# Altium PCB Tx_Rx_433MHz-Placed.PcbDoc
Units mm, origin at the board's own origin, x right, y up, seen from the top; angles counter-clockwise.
Board outline 100 x 100 mm, 4 copper layers (SIGNAL_1, SIGNAL_2, SIGNAL_3, SIGNAL_4), stack 1.58 mm thick; 85 components, 84 nets, 318 pads, 0 vias.
Unrouted connection lines stored in the file: 208.
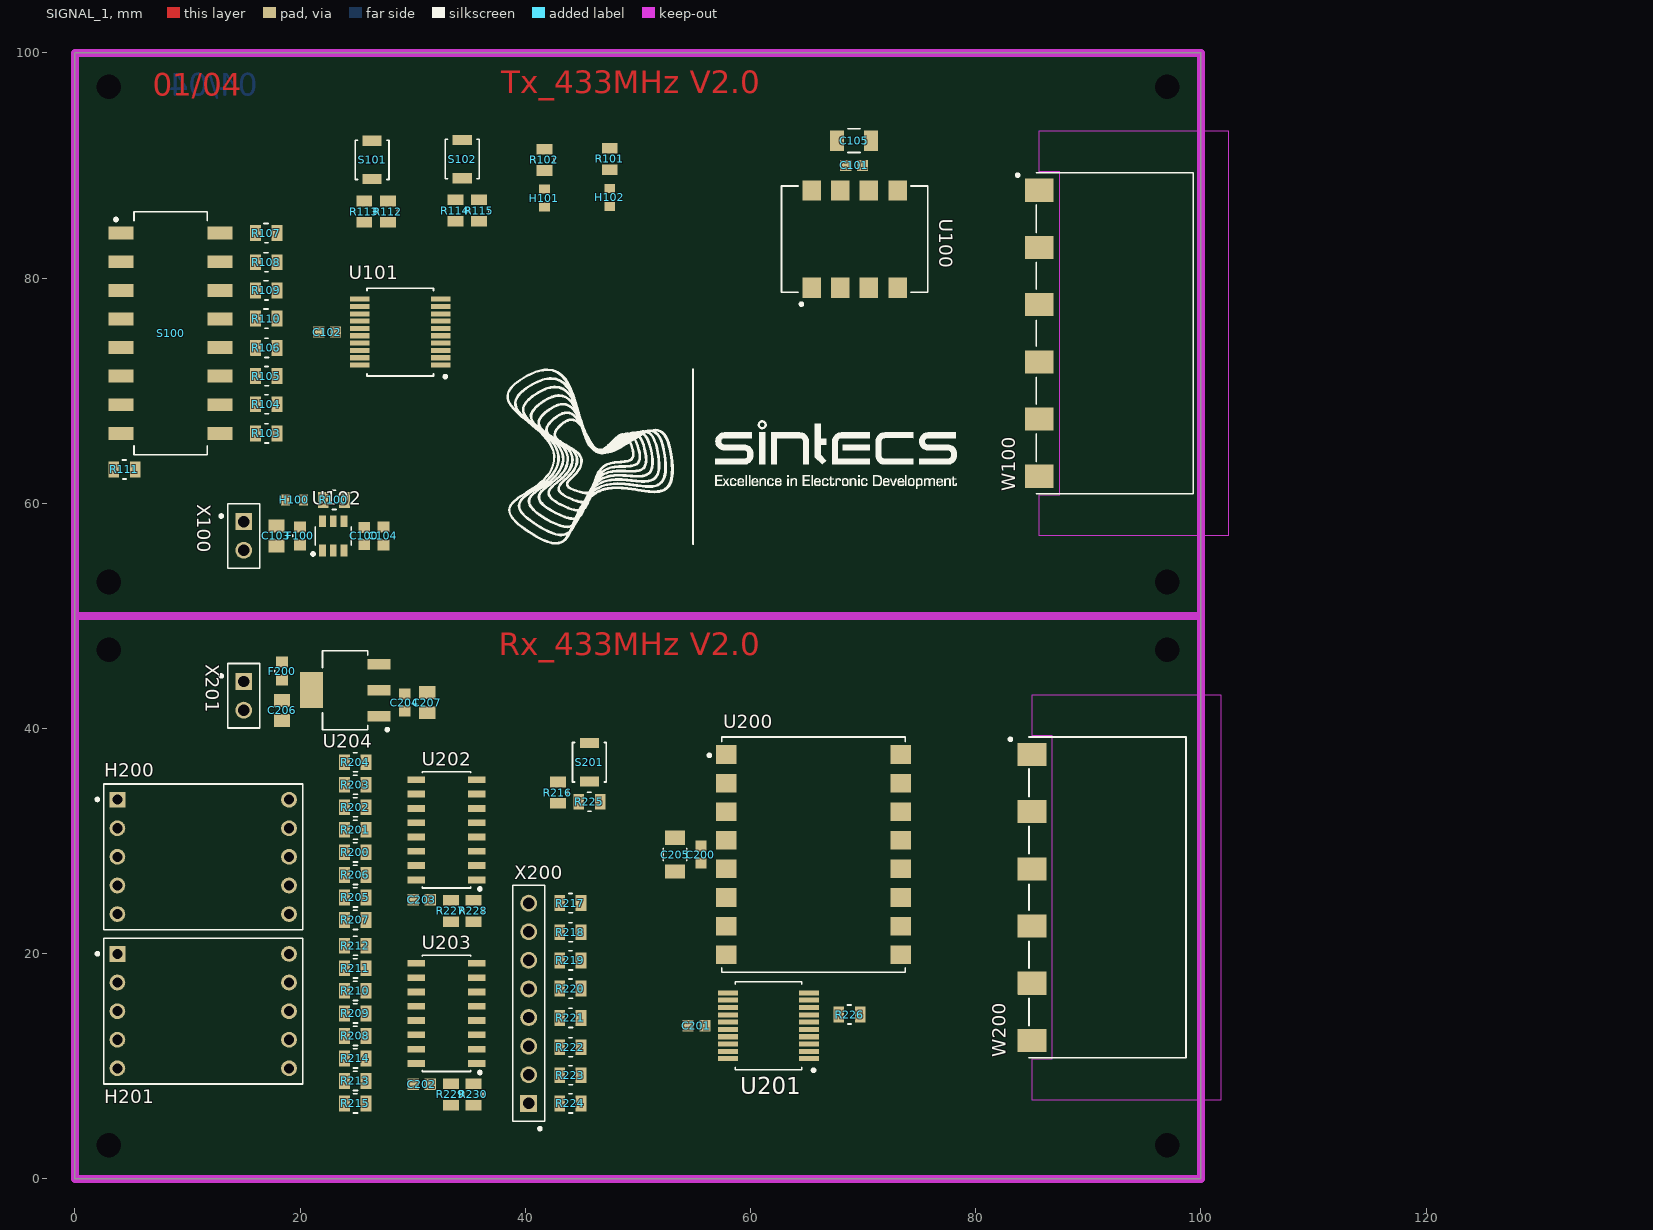
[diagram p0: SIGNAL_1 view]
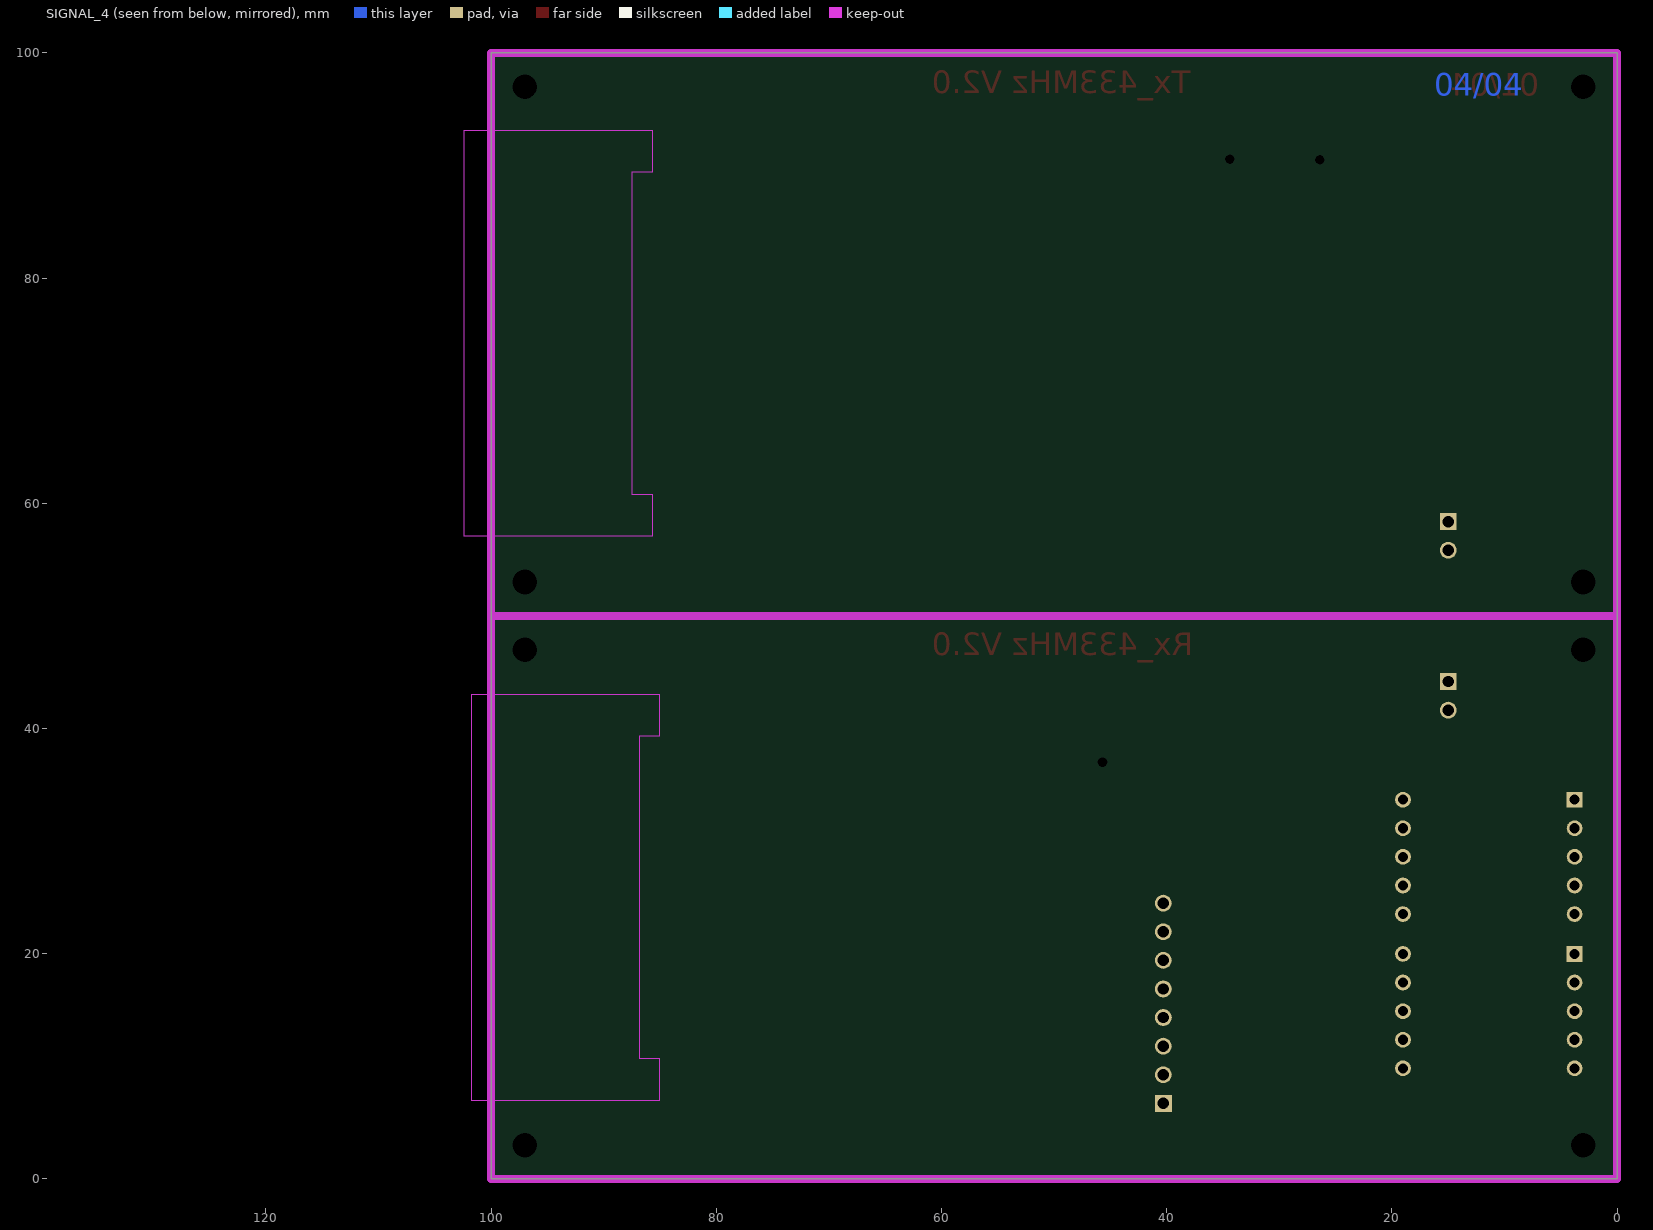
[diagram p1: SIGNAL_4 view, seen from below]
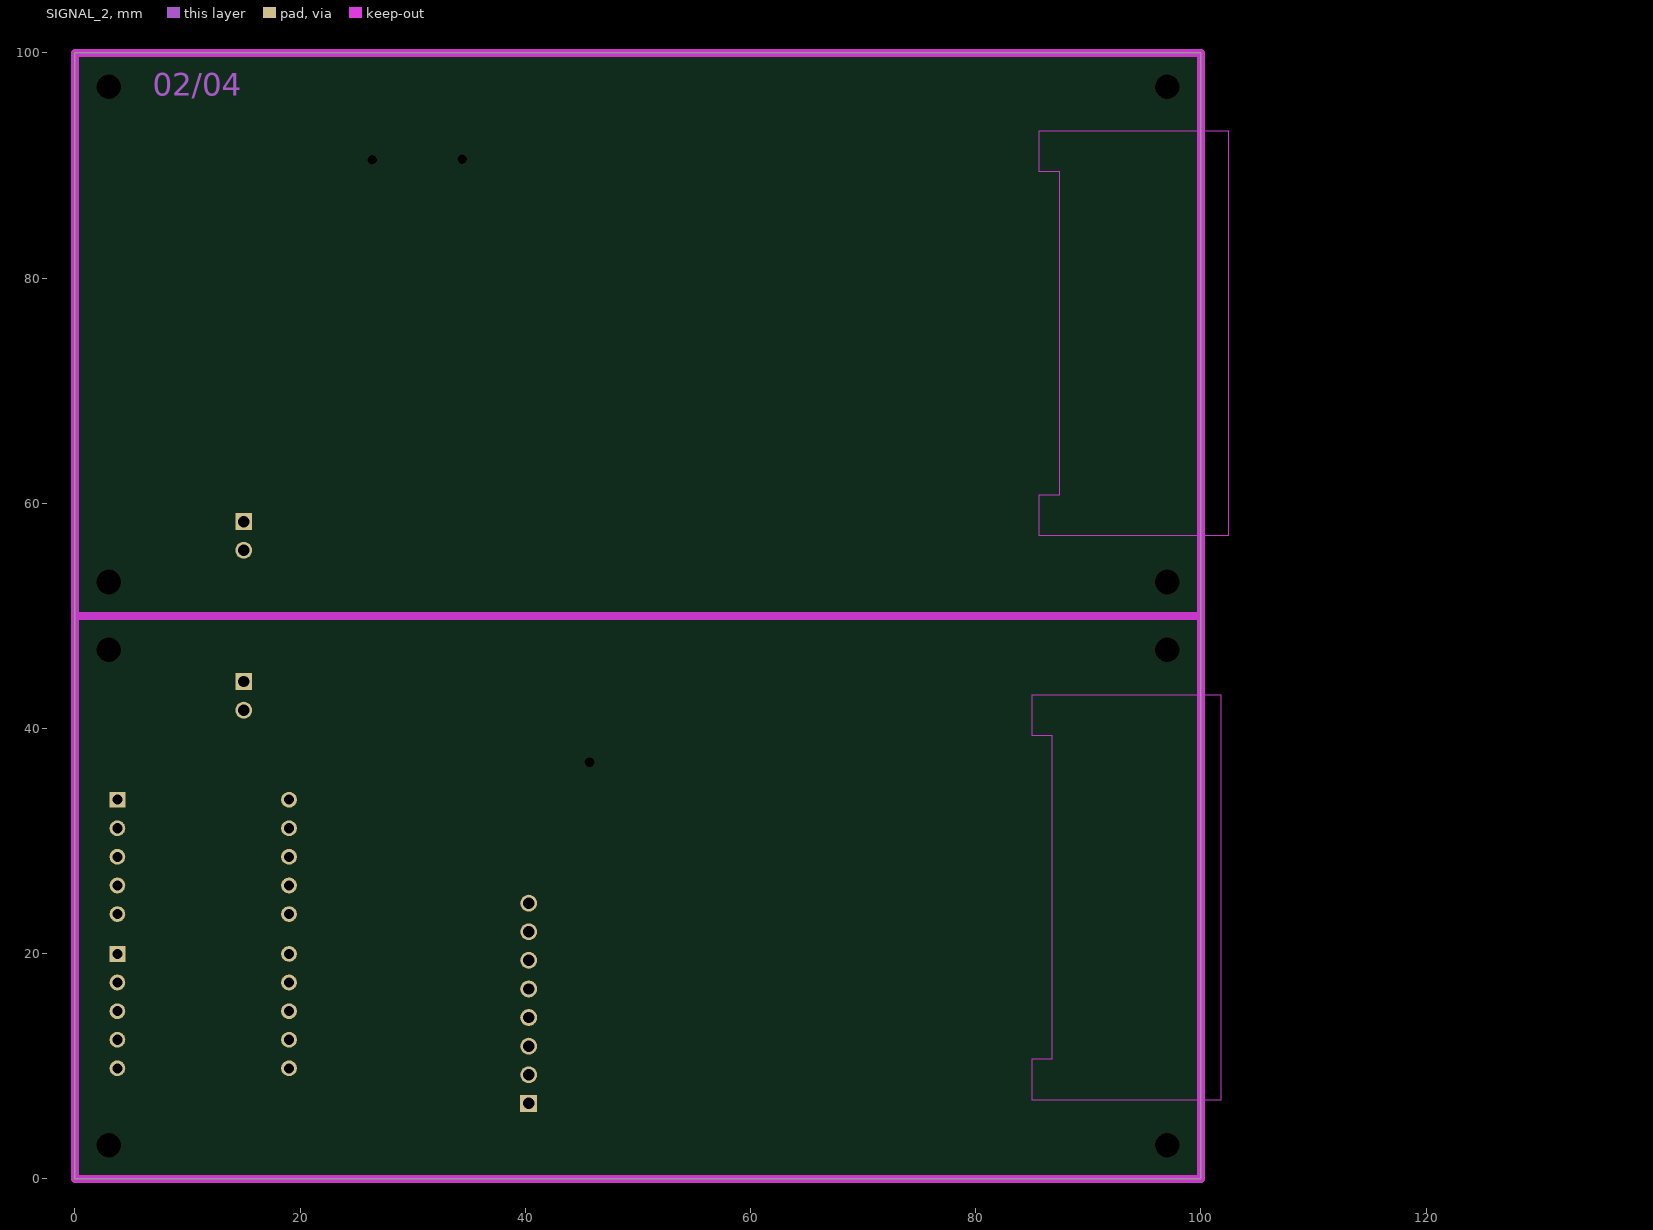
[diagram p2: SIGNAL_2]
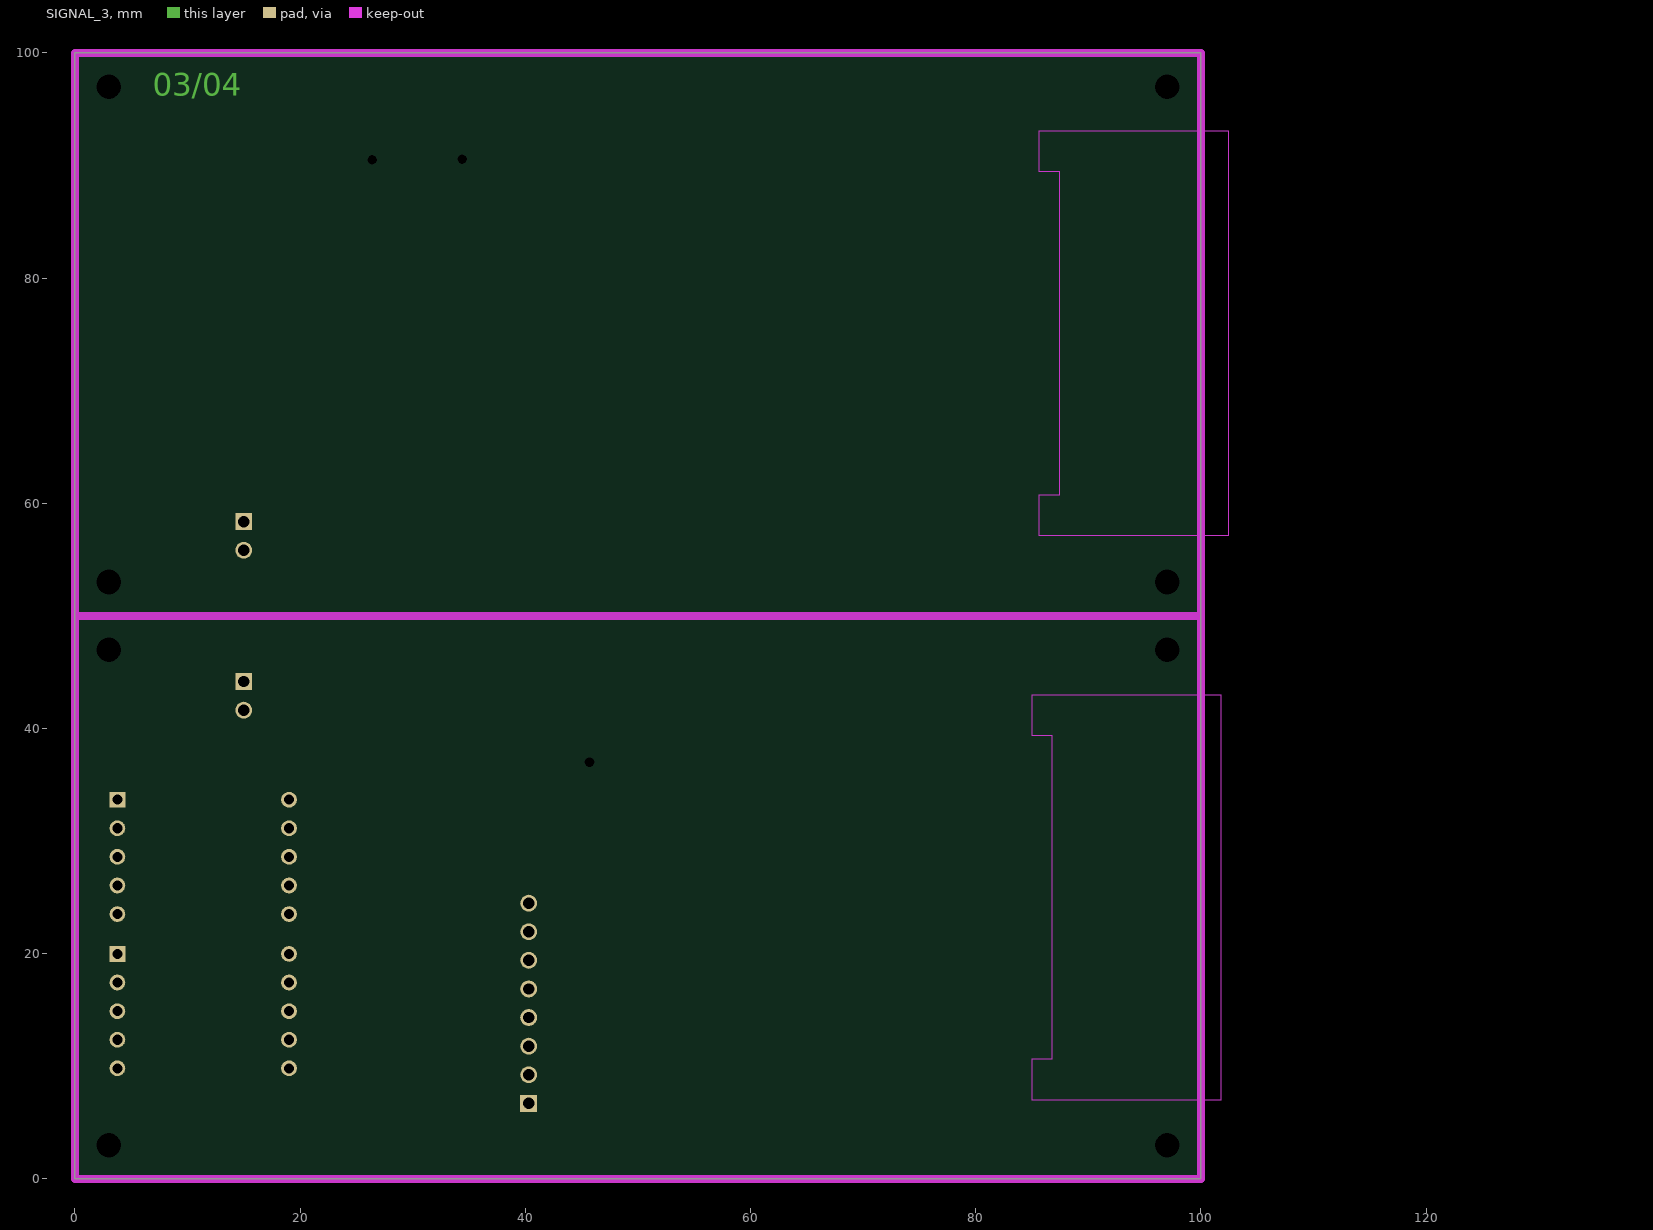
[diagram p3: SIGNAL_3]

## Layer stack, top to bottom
DIELECTRIC_1: solder mask 0.01, Dk 1
SIGNAL_1: signal copper 0.035
DIELECTRIC_3: prepreg 0.12, Dk 4.7
SIGNAL_2: signal copper 0.035
DIELECTRIC_5: prepreg 1.2, Dk 4.7
SIGNAL_3: signal copper 0.035
DIELECTRIC_7: prepreg 0.12, Dk 4.7
SIGNAL_4: signal copper 0.035
DIELECTRIC_9: solder mask 0.01, Dk 1

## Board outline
0,0 100,0 100,100 0,100

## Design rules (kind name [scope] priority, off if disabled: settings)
Clearance Clearance_50R [InNetClass('50R') vs Not Keepout] p1: gap=0.6 ignorepadtopadclearanceinfootprint=FALSE except(0.2: SMDPad-SMDPad)
Clearance [All] p2: gap=0.15 ignorepadtopadclearanceinfootprint=FALSE
ComponentClearance [All] p1: gap=0.1 collisioncheckmode=3 verticalgap=0.254 showdistances=FALSE
DiffPairsRouting [All] p1: maxlimit=0.254 minlimit=0.254 mostfreqgap=0.254 toplayer_minwidth=0.15 toplayer_maxwidth=0.3 toplayer_prefwidth=0.15 midlayer1_minwidth=0.15 midlayer1_maxwidth=0.3 midlayer1_prefwidth=0.15 midlayer2_minwidth=0.15 midlayer2_maxwidth=0.3 midlayer2_prefwidth=0.15 bottomlayer_minwidth=0.15 bottomlayer_maxwidth=0.3 bottomlayer_prefwidth=0.15 maxuncoupledlength=12.7
MinimumSolderMaskSliver [All] p1: minsoldermaskwidth=0.1
PolygonConnect [All] p1: thpad.connectstyle=Relief thpad.reliefconductorwidth=0.15 thpad.reliefentries=4 thpad.polygonreliefangle="90 Angle" thpad.airgapwidth=0.15 smdpad.connectstyle=Relief smdpad.reliefconductorwidth=0.15 smdpad.reliefentries=4 smdpad.polygonreliefangle="90 Angle" smdpad.airgapwidth=0.15 via.connectstyle=Direct via.reliefconductorwidth=0.127 via.reliefentries=2 via.polygonreliefangle="90 Angle" via.airgapwidth=0.152
RoutingVias [All] p1: holewidth=0.3 width=0.7 viastyle="Through Hole" minholewidth=0.3 minwidth=0.7 maxholewidth=0.3 maxwidth=0.7
SilkToSilkClearance [All] p1: silktosilkclearance=0.1
SolderMaskExpansion SolderMaskExpansion_Via [IsVia] p1: expansion=0.075 istentingtop=FALSE soldermaskfromhole=TRUE
SolderMaskExpansion [All] p2: expansion=0.1 istentingtop=FALSE
SupplyNets "Schematic Supply Nets_3" [InNet('3V3_RX')] p1: voltage=0.000
SupplyNets "Schematic Supply Nets_2" [InNet('GND_RX')] p2: voltage=0.000
SupplyNets "Schematic Supply Nets_1" [InNet('3V3_TX')] p3: voltage=0.000
SupplyNets "Schematic Supply Nets" [InNet('GND_TX')] p4: voltage=0.000
UnRoutedNet [All] p1: checkbadconnections=TRUE
Width "Width for 50E_SE" [InNetClass('50R')] p1: maxlimit=0.2 minlimit=0.185 preferedwidth=0.2 toplayer_minwidth=0.2 bottomlayer_minwidth=0.2 impedanceprofiledriven=TRUE impedanceprofileid={877E34D1-77DC-4DEE-A0FB-207FE4FBDA97} impedanceprofilevalue=50.000000 minimp=50.000000 maximp=50.000000 favimp=50.000000
Width [All] p2: maxlimit=1 minlimit=0.15 preferedwidth=0.2
25 further rules are at their usual default settings.

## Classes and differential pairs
net class 50R: RF_RX RF_TX
component class TX: C100 C101 C102 C103 C104 C105 F100 H100 H101 H102 R100 R101 R102 R103 R104 R105 R106 R107 R108 R109 R110 R111 R112 R113 R114 R115 S100 S101 S102 U100 U101 U102 W100 X100
component class RX: C200 C201 C202 C203 C204 C205 C206 C207 F200 H200 H201 R200 R201 R202 R203 R204 R205 R206 R207 R208 R209 R210 R211 R212 R213 R214 R215 R216 R217 R218 R219 R220 R221 R222 R223 R224 R225 R226 R227 R228 R229 R230 S201 U200 U201 U202 U203 U204 W200 X200 X201
polygon class "\"(Inherited)\"": GND_RX_L02_P002

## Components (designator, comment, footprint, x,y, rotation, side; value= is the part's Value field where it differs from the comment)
C100 "C_0603_1608X90_GENERIC" CAPC1608X90N_0603_GENERIC 25.7,57.1 r90 top value=100nF
C101 "C_0603_1608X90_GENERIC" CAPC1608X90N_0603_GENERIC 69.2,90 r0 top value=100nF
C102 "C_0603_1608X90_GENERIC" CAPC1608X90N_0603_GENERIC 22.4,75.2 r180 top value=100nF
C103 "C_0805_2012X150_GENERIC" CAPC2012X150N_0805_GENERIC 17.9,57.1 r270 top value=1uF
C104 "CL10A226MP8NUNE" CAPC1608X105N 27.4,57.1 r90 top value=4.7uF
C105 "C_1206_3216X190_GENERIC" CAPC3216X190N_1206_GENERIC 69.2,92.2 r0 top value=10uF
C200 "C_0603_1608X90_GENERIC" CAPC1608X90N_0603_GENERIC 55.6,28.8 r90 top value=100nF
C201 "C_0603_1608X90_GENERIC" CAPC1608X90N_0603_GENERIC 55.2,13.6 r180 top value=100nF
C202 "C_0603_1608X90_GENERIC" CAPC1608X90N_0603_GENERIC 30.8,8.4 r0 top value=100nF
C203 "C_0603_1608X90_GENERIC" CAPC1608X90N_0603_GENERIC 30.8,24.8 r0 top value=100nF
C204 "C_0603_1608X90_GENERIC" CAPC1608X90N_0603_GENERIC 29.3,42.3 r270 top value=100nF
C205 "C_1206_3216X190_GENERIC" CAPC3216X190N_1206_GENERIC 53.3,28.8 r90 top value=10uF
C206 "08051C104KAZ2A" CAPC2013X140N_AVX 18.398,41.6 r270 top value=10uF
C207 "08051C104KAZ2A" CAPC2013X140N_AVX 31.3,42.3 r270 top value=10uF
F100 "0467XXXX" RESC1608X60N_0603_GENERIC 20,57.1 r270 top value=500mA
F200 "0467XXXX" RESC1608X60N_0603_GENERIC 18.4,45.1 r90 top value=500mA
H100 "KP-1608SGC" LEDC1608X110N 19.5,60.3 r180 top
H101 "KP-1608SGC" LEDC1608X110N 41.7,87.1 r90 top
H102 "KP-1608SGC" LEDC1608X110N 47.5,87.175 r90 top
H200 "HDSP-5XXX" BROADCOM_HDSP-5XXX 11.4,28.6 r0 top
H201 "HDSP-5XXX" BROADCOM_HDSP-5XXX 11.4,14.9 r0 top
R100 "R_0805_2012X60_GENERIC" RESC2012X60N_0805_GENERIC 23,60.3 r180 top value=120R
R101 "R_0805_2012X60_GENERIC" RESC2012X60N_0805_GENERIC 47.5,90.575 r90 top value=120R
R102 "R_0805_2012X60_GENERIC" RESC2012X60N_0805_GENERIC 41.7,90.5 r90 top value=120R
R103 "R_0805_2012X60_GENERIC" RESC2012X60N_0805_GENERIC 17,66.2 r180 top value=100K
R104 "R_0805_2012X60_GENERIC" RESC2012X60N_0805_GENERIC 17,68.8 r180 top value=100K
R105 "R_0805_2012X60_GENERIC" RESC2012X60N_0805_GENERIC 17,71.3 r180 top value=100K
R106 "R_0805_2012X60_GENERIC" RESC2012X60N_0805_GENERIC 17,73.8 r180 top value=100K
R107 "R_0805_2012X60_GENERIC" RESC2012X60N_0805_GENERIC 17,84 r0 top value=100K
R108 "R_0805_2012X60_GENERIC" RESC2012X60N_0805_GENERIC 17,81.4 r0 top value=100K
R109 "R_0805_2012X60_GENERIC" RESC2012X60N_0805_GENERIC 17,78.9 r0 top value=100K
R110 "R_0805_2012X60_GENERIC" RESC2012X60N_0805_GENERIC 17,76.4 r0 top value=100K
R111 "R_0805_2012X60_GENERIC" RESC2012X60N_0805_GENERIC 4.4,63 r0 top value=1K
R112 "R_0805_2012X60_GENERIC" RESC2012X60N_0805_GENERIC 27.8,85.9 r90 top value=100K
R113 "R_0805_2012X60_GENERIC" RESC2012X60N_0805_GENERIC 25.7,85.9 r270 top value=1K
R114 "R_0805_2012X60_GENERIC" RESC2012X60N_0805_GENERIC 33.8,86 r270 top value=1K
R115 "R_0805_2012X60_GENERIC" RESC2012X60N_0805_GENERIC 35.9,86 r90 top value=100K
R200 "R_0805_2012X60_GENERIC" RESC2012X60N_0805_GENERIC 24.9,29.001 r180 top value=120R
R201 "R_0805_2012X60_GENERIC" RESC2012X60N_0805_GENERIC 24.9,31.001 r180 top value=120R
R202 "R_0805_2012X60_GENERIC" RESC2012X60N_0805_GENERIC 24.9,33.001 r180 top value=120R
R203 "R_0805_2012X60_GENERIC" RESC2012X60N_0805_GENERIC 24.9,35.001 r180 top value=120R
R204 "R_0805_2012X60_GENERIC" RESC2012X60N_0805_GENERIC 24.9,37.002 r180 top value=120R
R205 "R_0805_2012X60_GENERIC" RESC2012X60N_0805_GENERIC 24.9,25 r180 top value=120R
R206 "R_0805_2012X60_GENERIC" RESC2012X60N_0805_GENERIC 24.9,27 r180 top value=120R
R207 "R_0805_2012X60_GENERIC" RESC2012X60N_0805_GENERIC 24.9,23 r180 top value=120R
R208 "R_0805_2012X60_GENERIC" RESC2012X60N_0805_GENERIC 24.9,12.7 r180 top value=120R
R209 "R_0805_2012X60_GENERIC" RESC2012X60N_0805_GENERIC 24.9,14.7 r180 top value=120R
R210 "R_0805_2012X60_GENERIC" RESC2012X60N_0805_GENERIC 24.9,16.701 r180 top value=120R
R211 "R_0805_2012X60_GENERIC" RESC2012X60N_0805_GENERIC 24.9,18.701 r180 top value=120R
R212 "R_0805_2012X60_GENERIC" RESC2012X60N_0805_GENERIC 24.9,20.701 r180 top value=120R
R213 "R_0805_2012X60_GENERIC" RESC2012X60N_0805_GENERIC 24.9,8.7 r180 top value=120R
R214 "R_0805_2012X60_GENERIC" RESC2012X60N_0805_GENERIC 24.9,10.7 r180 top value=120R
R215 "R_0805_2012X60_GENERIC" RESC2012X60N_0805_GENERIC 24.9,6.7 r180 top value=120R
R216 "R_0805_2012X60_GENERIC" RESC2012X60N_0805_GENERIC 42.9,34.3 r270 top value=100K
R217 "R_0805_2012X60_GENERIC" RESC2012X60N_0805_GENERIC 44,24.5 r180 top value=1K
R218 "R_0805_2012X60_GENERIC" RESC2012X60N_0805_GENERIC 44,21.9 r180 top value=1K
R219 "R_0805_2012X60_GENERIC" RESC2012X60N_0805_GENERIC 44,19.4 r180 top value=1K
R220 "R_0805_2012X60_GENERIC" RESC2012X60N_0805_GENERIC 44,16.9 r180 top value=1K
R221 "R_0805_2012X60_GENERIC" RESC2012X60N_0805_GENERIC 44,14.3 r180 top value=1K
R222 "R_0805_2012X60_GENERIC" RESC2012X60N_0805_GENERIC 44,11.7 r180 top value=1K
R223 "R_0805_2012X60_GENERIC" RESC2012X60N_0805_GENERIC 44,9.2 r180 top value=1K
R224 "R_0805_2012X60_GENERIC" RESC2012X60N_0805_GENERIC 44,6.7 r180 top value=1K
R225 "R_0805_2012X60_GENERIC" RESC2012X60N_0805_GENERIC 45.7,33.5 r0 top value=1K
R226 "R_0805_2012X60_GENERIC" RESC2012X60N_0805_GENERIC 68.8,14.6 r0 top value=100K
R227 "R_0805_2012X60_GENERIC" RESC2012X60N_0805_GENERIC 33.4,23.8 r270 top value=100K
R228 "R_0805_2012X60_GENERIC" RESC2012X60N_0805_GENERIC 35.4,23.8 r270 top value=100K
R229 "R_0805_2012X60_GENERIC" RESC2012X60N_0805_GENERIC 33.4,7.5 r270 top value=100K
R230 "R_0805_2012X60_GENERIC" RESC2012X60N_0805_GENERIC 35.4,7.5 r270 top value=100K
S100 "418121270808" WE_418121270808 8.5,75.1 r0 top
S101 "B3U_1000P_B" OMRON_B3U_1000P_B 26.4,90.5 r90 top
S102 "B3U_1000P_B" OMRON_B3U_1000P_B 34.402,90.57 r90 top
S201 "B3U_1000P_B" OMRON_B3U_1000P_B 45.7,37 r270 top
U100 "TXM-433-LR" LINX_TXM-433-LR 69.25,83.45 r90 top
U101 "LICAL-ENC-MS001" SOP65P780X200-20N 28.9,75.2 r180 top
U102 "MAX8881EU" SOT95P280X100-6N 22.95,57.1 r90 top
U200 "RXM-433-LR" LINX_RXM-433-LR 65.6,28.8 r0 top
U201 "LICAL-DEC-MS001" SOP65P780X200-20N 61.6,13.6 r180 top
U202 "CD74HC4511M" SOIC127P600X175-16N 33,31 r180 top
U203 "CD74HC4511M" SOIC127P600X175-16N 33,14.7 r180 top
U204 "LM1117MPX" SOT230P700X180-4N 25.498,43.4 r180 top
W100 "ANT-433-SP" LINX_ANT-433-SP 85.65,75.1 r270 top
W200 "ANT-433-SP" LINX_ANT-433-SP 85,25 r270 top
X100 "M20_9770242" HARWIN_M20_9770242 15,57.1 r270 top
X200 "M20_9770842" HARWIN_M20_9770842 40.3,15.6 r90 top
X201 "M20_9770242" HARWIN_M20_9770242 15,42.9 r270 top

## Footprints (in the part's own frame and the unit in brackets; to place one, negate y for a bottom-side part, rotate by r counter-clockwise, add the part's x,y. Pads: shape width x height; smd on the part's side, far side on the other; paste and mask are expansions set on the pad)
BROADCOM_HDSP-5XXX [mm]
  rrect1% 1.4x1.4 hole 0.9 paste-2539.97 mask-0.713: 1(-7.62,5.08)
  round 1.4 hole 0.9 paste-2539.97 mask-0.713: 2(-7.62,2.54) 3(-7.62,0) 4(-7.62,-2.54) 5(-7.62,-5.08) 6(7.62,-5.08) 7(7.62,-2.54) 8(7.62,0) 9(7.62,2.54) 10(7.62,5.08)
  silkscreen extent -9.53,-6.47 8.83,6.48, body extent -8.55,-6.2 8.55,6.2, height 8
CAPC1608X90N_0603_GENERIC [mm]
  rrect1% 1x1 smd paste+0 mask-0.513: 1(-0.75,0) 2(0.75,0)
  body extent -0.8,-0.4 0.8,0.4, height 0.8
CAPC1608X105N [mm]
  rrect1% 1x1.05 smd paste+0 mask-0.538: 1(-0.8,0) 2(0.8,0)
  body extent -0.8,-0.4 0.8,0.4, height 0.8
CAPC2012X150N_0805_GENERIC [mm]
  rrect1% 1.15x1.45 smd paste+0 mask-0.738: 1(-0.9,0) 2(0.9,0)
  body extent -1,-0.63 1,0.63, height 1
CAPC2013X140N_AVX [mm]
  rrect1% 1.15x1.45 smd paste+0 mask-0.738: 1(-0.9,0) 2(0.9,0)
  body extent -1,-0.63 1,0.63, height 1
CAPC3216X190N_1206_GENERIC [mm]
  rrect1% 1.25x1.8 smd paste+0 mask-0.913: 1(-1.5,0) 2(1.5,0)
  silkscreen extent -0.55,-1.05 0.55,1.05, body extent -1.6,-0.8 1.6,0.8, height 1.2
HARWIN_M20_9770242 [mm]
  rrect1% 1.5x1.5 hole 1 paste-2539.97 mask-0.763: 1(-1.27,0)
  round 1.5 hole 1 paste-2539.97 mask-0.763: 2(1.27,0)
  silkscreen extent -2.87,-2.13 2.86,1.42, body extent -2.54,-1.27 2.54,1.27, height 8.34
HARWIN_M20_9770842 [mm]
  rrect1% 1.5x1.5 hole 1 paste-2539.97 mask-0.763: 1(-8.89,0)
  round 1.5 hole 1 paste-2539.97 mask-0.763: 2(-6.35,0) 3(-3.81,0) 4(-1.27,0) 5(1.27,0) 6(3.81,0) 7(6.35,0) 8(8.89,0)
  silkscreen extent -11.26,-1.42 10.48,1.42, body extent -10.16,-1.27 10.16,1.27, height 8.34
LEDC1608X110N [mm]
  rrect1% 0.8x0.95 smd paste+0 mask-0.488: 1(-0.8,0) 2(0.8,0)
  body extent -0.8,-0.4 0.81,0.4, height 0.75
LINX_ANT-433-SP [mm]
  rrect1% 2.05x2.55 smd paste+0 mask-1.288: 1(-12.7,0) 2(-7.62,0) 3(-2.54,0) 4(2.54,0) 5(7.62,0) 6(12.7,0)
  Keep-Out Layer region: 14.35,0 14.35,1.8 -14.35,1.8 -14.35,0 -18,0 -18,16.78 18,16.78 18,0
  silkscreen extent -14.24,-2.04 14.24,13.67, body extent -13.97,-0.38 13.97,13.34, height 1.52
LINX_RXM-433-LR [mm]
  rrect1% 1.8x1.65 smd paste+0 mask-0.913: 1(-7.747,8.89) 2(-7.747,6.35) 3(-7.747,3.81) 4(-7.747,1.27) 5(-7.747,-1.27) 6(-7.747,-3.81) 7(-7.747,-6.35) 8(-7.747,-8.89) 9(7.747,-8.89) 10(7.747,-6.35) 11(7.747,-3.81) 12(7.747,-1.27) 13(7.747,1.27) 14(7.747,3.81) 15(7.747,6.35) 16(7.747,8.89)
  silkscreen extent -9.38,-10.45 8.15,10.45, body extent -8,-10.3 8,10.4, height 3.3
LINX_TXM-433-LR [mm]
  rrect1% 1.8x1.65 smd paste+0 mask-0.913: 1(-4.318,3.81) 2(-4.318,1.27) 3(-4.318,-1.27) 4(-4.318,-3.81) 5(4.318,-3.81) 6(4.318,-1.27) 7(4.318,1.27) 8(4.318,3.81)
  silkscreen extent -5.89,-6.5 4.72,6.5, body extent -4.6,-6.4 4.6,6.4, height 3.3
OMRON_B3U_1000P_B [mm]
  rrect1% 0.9x1.7 smd paste+0 mask-0.863: 1(-1.7,0) 2(1.7,0)
  round 0 hole 0.85 unplated paste-2539.97: ""(0,0)
  silkscreen extent -1.75,-1.5 1.75,1.5, body extent -2,-1.25 2,1.25, height 1.75
RESC1608X60N_0603_GENERIC [mm]
  rrect1% 0.95x1.05 smd paste+0 mask-0.538: 1(-0.8,0) 2(0.8,0)
  silkscreen extent -0.08,-0.65 0.08,0.65, body extent -0.8,-0.4 0.8,0.4, height 0.5
RESC2012X60N_0805_GENERIC [mm]
  rrect1% 0.95x1.4 smd paste+0 mask-0.713: 1(-0.95,0) 2(0.95,0)
  silkscreen extent -0.2,-0.85 0.15,0.85, body extent -1,-0.63 1,0.63, height 0.5
SOIC127P600X175-16N [mm]
  rrect1% 1.55x0.6 smd paste+0 mask-0.788: 1(-2.7,4.445) 2(-2.7,3.175) 3(-2.7,1.905) 4(-2.7,0.635) 5(-2.7,-0.635) 6(-2.7,-1.905) 7(-2.7,-3.175) 8(-2.7,-4.445) 9(2.7,-4.445) 10(2.7,-3.175) 11(2.7,-1.905) 12(2.7,-0.635) 13(2.7,0.635) 14(2.7,1.905) 15(2.7,3.175) 16(2.7,4.445)
  silkscreen extent -3.1,-5.16 2.15,5.38, body extent -3,-4.95 3,4.95, height 1.75
SOP65P780X200-20N [mm]
  rrect1% 1.75x0.45 smd paste+0 mask-0.888: 1(-3.6,2.925) 2(-3.6,2.275) 3(-3.6,1.625) 4(-3.6,0.975) 5(-3.6,0.325) 6(-3.6,-0.325) 7(-3.6,-0.975) 8(-3.6,-1.625) 9(-3.6,-2.275) 10(-3.6,-2.925) 11(3.6,-2.925) 12(3.6,-2.275) 13(3.6,-1.625) 14(3.6,-0.975) 15(3.6,-0.325) 16(3.6,0.325) 17(3.6,0.975) 18(3.6,1.625) 19(3.6,2.275) 20(3.6,2.925)
  silkscreen extent -4.13,-3.9 2.95,4.08, body extent -3.93,-3.6 3.93,3.6, height 2
SOT95P280X100-6N [mm]
  rrect1% 1.05x0.6 smd paste+0 mask-0.538: 1(-1.3,0.95) 2(-1.3,0) 3(-1.3,-0.95) 4(1.3,-0.95) 5(1.3,0) 6(1.3,0.95)
  silkscreen extent -1.73,-1.6 0.8,1.92, body extent -1.28,-1.45 1.28,1.45, height 1.45
SOT230P700X180-4N [mm]
  rrect1% 2.05x0.95 smd paste+0 mask-1.038: 1(-1.5,2.3) 2(-1.5,0) 3(-1.5,-2.3)
  rrect1% 2.05x3.2 smd paste+0 mask-1.613: 4(4.5,0)
  silkscreen extent -2.37,-3.5 3.5,3.63, body extent -1.98,-3.25 5.02,3.25, height 1.8
WE_418121270808 [mm]
  rrect1% 2.2x1.15 smd paste+0 mask-1.113: 1(-4.4,8.89) 2(-4.4,6.35) 3(-4.4,3.81) 4(-4.4,1.27) 5(-4.4,-1.27) 6(-4.4,-3.81) 7(-4.4,-6.35) 8(-4.4,-8.89) 9(4.4,-8.89) 10(4.4,-6.35) 11(4.4,-3.81) 12(4.4,-1.27) 13(4.4,1.27) 14(4.4,3.81) 15(4.4,6.35) 16(4.4,8.89)
  silkscreen extent -4.97,-10.78 3.25,10.78, body extent -4.9,-10.63 4.9,10.63, height 4.32

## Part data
C100 C101 C102 C200 C201 C202 C203 C204: "100nF 25V 10%", Capacitance=100000, Dielectric=X7R, Manufacturer=MURATA, MPN=GRM188R71E104KA01D, Package=0603, Part Name="Ceramic chip capacitor 0603-1608x90, generic", Tolerance=10, Voltage=25V
C103: "1µF 25V 10%", Capacitance=1000000, Dielectric=X7R, Manufacturer=AVX, MPN=08053C105K4Z2A, Package=0805, Part Name="Ceramic chip capacitor 0805-2012x150, generic", Tolerance=10, Voltage=25V
C104: "4.7uF 25V 10%", Alternate Manufacturer=SAMSUNG, Alternate MPN=CL10A475KA8NQNC, Capacitance=4700000, Dielectric=X5R, Manufacturer=AVX, MPN=06033D475KAT2A, Package=0603, Part Name="CAP 22uF 10V 0603 X5R", Tolerance=10, Voltage=25V
C105 C205: "10uF 25V 10%", Capacitance=10000000, Dielectric=X7R, Manufacturer=AVX, Max Temp=+125, Min Temp=-55, MPN=12063C106KAT2A, Package=1206, Part Name="Cheramic chip capacitor 1206-3216x190, generic", Tolerance=10, Voltage=25V
C206 C207: "10uF 25V 10%", Capacitance=10000000, Dielectric=X5R, Manufacturer=AVX, MPN=08053D106KAT2A, Package=0805, Part Name="0805 chip 100nF 10% 100V X7R", Tolerance=10, Voltage=25V
F100 F200: "Thin film 0603 fuse very fast acting", Current=0.5, Manufacturer=LITTELFUSE, Max Temp=+90, Min Temp=-55, MPN=0467.500NRHF, Package=0603, Part Name="Thin film 0603 very fast acting", Voltage=32V
H100 H101 H102: "LED Green", Current=20mA, Manufacturer=KINGBRIGHT, MPN=APT-1608SGC, Package=0603, Part Name="SMD LED lamp, Green"
H200 H201: "7 Segment Display Module Red, 1,85V, 20mA. THT", Color=Red, Manufacturer=BROADCOM, Max Temp=85, Min Temp=-25, MPN=HDSP-515A, Part Name="Single Digit LED Numeric Display, Blue color"
R100 R101 R102 R200 R201 R202 R203 R204 R205 R206 R207 R208 R209 R210 R211 R212 R213 R214 R215: "0.125W 5% 120R 50V", Manufacturer=YAGEO, MPN=RC0805JR-07120RL, Package=0805, Part Name="resistor_0805-2012x60 generic", Tolerance=5%
R103 R104 R105 R106 R107 R108 R109 R110 R112 R115 R216 R226 R227 R228 R229 R230: "0.125W 5% 100K 50V", Manufacturer=YAGEO, MPN=RC0805JR-07100KL, Package=0805, Part Name="resistor_0805-2012x60 generic", Tolerance=5%
R111 R113 R114 R217 R218 R219 R220 R221 R222 R223 R224 R225: "Resistor_1K_1%_0805", Manufacturer=MULTICOMP, MPN=MCPWR05FTEW1001, Package=0805, Part Name="resistor_0805-2012x60 generic", Tolerance=1%
S100: "Dip Switch SPST 8 Position Surface Mount Slide (Standard) Actuator 25mA 24VDC", Current=25mA, Manufacturer="WURTH ELEKTRONIK", Max Temp=85, Min Temp=-40, Part Name="Dip Switch SPST 8 Position Surface Mount", Voltage=24
S101 S102 S201: "Ultra-small Tactile Switch", Manufacturer=OMRON, Max Temp=0, MPN=B3U-1000P-B
U100: "LR Series Transmitter, Low Voltage, Low Power", Manufacturer="Linx Technologies", Max Temp=85, Min Temp=-40, Package=custom
U101: "MS Series Remote Controler Encoder, Low Voltage, Low Power", Manufacturer="LINX TECHNOLOGIES", Max Temp=85, Min Temp=-40, Package=SOP-20
U102: "Low Dropout Linear Regulator with enable and power good, 3.3V, 6 pin SOT23", Manufacturer=MAXIM, Max Temp=85, Min Temp=-40, MPN=MAX8881EUT33+T, Output Current=0.20A, Package=SOT23-6, Part Name="Low Dropout Linear Regulator, 6 pin SOT23"
U200: "LR Series Receiver, Low Voltage, Low Power", Manufacturer="Linx Technologies", Max Temp=70, Min Temp=-40, Package=custom
U201: "MS Series Remote Controler Decoder, Low Voltage, Low Power", Manufacturer="LINX TECHNOLOGIES", Max Temp=85, Min Temp=-40, MPN=LICAL-DEC-MS001-T, Package=SOP-20
U202 U203: "Leddriver BCD to 7 segment 1 Digit", Manufacturer="TEXAS INSTRUMENTS", Max Temp=125, Min Temp=-55, Package=SOIC-16N
U204: "3.3V/1A fixed regulator", Manufacturer=ON-SEMI, MPN=NCP1117LPST33T3G, Package=SOT, Part Name="800mA Low-Dropout Linear Regulator, SOT223"
W100 W200: "433MHz 50 Ohm Antenna module", Manufacturer="Linx Technologies", Max Temp=130, Min Temp=-40, Package=custom
X100 X201: "1x2 pin 2.54 mm pitch vertical header", Manufacturer=HARWIN, MPN=M20-9770242, Package=header, Part Name=STD_HEADER_1x2_2.54_THT
X200: "1x8 pin 2.54 mm pitch vertical header", Manufacturer=HARWIN, MPN=M20-9770842, Package=header, Part Name=STD_HEADER_1x8_2.54_THT

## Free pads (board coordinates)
  round 0 hole 2.2 unplated paste-2539.97 mask+1.6: ""(3,3) ""(3,47) ""(3,53) ""(3,97) ""(97,3) ""(97,47) ""(97,53) ""(97,97)
  round 0.025 smd far side paste-2539.97 mask-127: ""(7,6.05) ""(80.8,5.2) ""(136.95,83.95)

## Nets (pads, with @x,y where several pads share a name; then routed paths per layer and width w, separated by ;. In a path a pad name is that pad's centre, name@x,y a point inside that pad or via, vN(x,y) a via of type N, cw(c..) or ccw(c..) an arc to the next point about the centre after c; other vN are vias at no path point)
3V3_RX: C200.1 C201.1 C202.1 C203.1 C204.1 C205.1 C207.1 R215.1 R226.2 R227.2 R228.2 R229.2 R230.2 S201.1 U200.5 U201.15 U201.16 U202.16 U203.16 U204.2 U204.4
3V3_TX: C100.1 C101.1 C102.1 C104.1 C105.1 R100.1 R111.2 S101.2 S102.2 U100.4 U100.7 U101.15 U101.16 U102.3 U102.4
DEC_MODE_IND: R207.1 U201.10
GND_RX: C200.2 C201.2 C202.2 C203.2 C204.2 C205.2 C206.2 C207.2 H200.3 H200.8 H201.3 H201.8 R216.1 U200.4 U200.15 U201.3 U201.4 U201.5 U201.6 U201.8 U202.5 U202.8 U203.5 U203.8 U204.1 W200.2 W200.3 W200.4 W200.5 W200.6 X201.2
GND_TX: C100.2 C101.2 C102.2 C103.2 C104.2 C105.2 H100.2 R101.2 R102.2 R103.1 R104.1 R105.1 R106.1 R107.2 R108.2 R109.2 R110.2 R112.1 R115.1 U100.1 U100.3 U100.6 U101.3 U101.4 U101.5 U101.6 U101.7 U102.2 W100.2 W100.3 W100.4 W100.5 W100.6 X100.2
NetC103_1: C103.1 F100.1 X100.1
NetC206_1: C206.1 F200.1 X201.1
NetF100_2: F100.2 U102.1 U102.5
NetF200_2: F200.2 U204.3
NetH100_1: H100.1 R100.2 U102.6
NetH101_1: H101.1 U100.8 U101.8
NetH101_2: H101.2 R102.1
NetH102_1: H102.1 U101.10
NetH102_2: H102.2 R101.1
NetH200_1: H200.1 R204.2
NetH200_2: H200.2 R203.2
NetH200_4: H200.4 R202.2
NetH200_5: H200.5 R207.2
NetH200_6: H200.6 R201.2
NetH200_7: H200.7 R200.2
NetH200_9: H200.9 R205.2
NetH200_10: H200.10 R206.2
NetH201_1: H201.1 R212.2
NetH201_2: H201.2 R211.2
NetH201_4: H201.4 R210.2
NetH201_5: H201.5 R215.2
NetH201_6: H201.6 R209.2
NetH201_7: H201.7 R208.2
NetH201_9: H201.9 R213.2
NetH201_10: H201.10 R214.2
NetR103_2: R103.2 S100.9 U101.20
NetR104_2: R104.2 S100.10 U101.19
NetR105_2: R105.2 S100.11 U101.18
NetR106_2: R106.2 S100.12 U101.17
NetR107_1: R107.1 S100.16 U101.1
NetR108_1: R108.1 S100.15 U101.2
NetR109_1: R109.1 S100.14 U101.13
NetR110_1: R110.1 S100.13 U101.14
NetR111_1: R111.1 S100.1 S100.2 S100.3 S100.4 S100.5 S100.6 S100.7 S100.8
NetR112_2: R112.2 R113.1 S101.1
NetR113_2: R113.2 U101.12
NetR114_1: R114.1 R115.2 S102.1
NetR114_2: R114.2 U101.11
NetR200_1: R200.1 U202.13
NetR201_1: R201.1 U202.12
NetR202_1: R202.1 U202.11
NetR203_1: R203.1 U202.10
NetR204_1: R204.1 U202.9
NetR205_1: R205.1 U202.15
NetR206_1: R206.1 U202.14
NetR208_1: R208.1 U203.13
NetR209_1: R209.1 U203.12
NetR210_1: R210.1 U203.11
NetR211_1: R211.1 U203.10
NetR212_1: R212.1 U203.9
NetR213_1: R213.1 U203.15
NetR214_1: R214.1 U203.14
NetR216_2: R216.2 R225.1 S201.2
NetR217_1: R217.1 U201.1
NetR217_2: R217.2 U202.7 X200.8
NetR218_1: R218.1 U201.2
NetR218_2: R218.2 U202.1 X200.7
NetR219_1: R219.1 U201.13
NetR219_2: R219.2 U202.2 X200.6
NetR220_1: R220.1 U201.14
NetR220_2: R220.2 U202.6 X200.5
NetR221_1: R221.1 U201.17
NetR221_2: R221.2 U203.7 X200.4
NetR222_1: R222.1 U201.18
NetR222_2: R222.2 U203.1 X200.3
NetR223_1: R223.1 U201.19
NetR223_2: R223.2 U203.2 X200.2
NetR224_1: R224.1 U201.20
NetR224_2: R224.2 U203.6 X200.1
NetR225_2: R225.2 U201.11
NetR226_1: R226.1 U201.7
NetR227_1: R227.1 U202.4
NetR228_1: R228.1 U202.3
NetR229_1: R229.1 U203.4
NetR230_1: R230.1 U203.3
NetU100_2: U100.2 U101.9
RF_RX: U200.16 W200.1
RF_TX: U100.5 W100.1
RX_DATA: U200.8 U201.12
pads on no net: S101. S102. S201. U200.1 U200.2 U200.3 U200.6 U200.7 U200.9 U200.10 U200.11 U200.12 U200.13 U200.14 U201.9

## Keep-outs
Keep-Out Layer:
  lines w0.7: 0,50 100,50 ; 0,0 0,100 100,100 100,0 0,0

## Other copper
SIGNAL_1:
  pour cut-out: 99.1,3 ccw(c97,3) 97,5.1 ccw(c97,3) 94.9,3 ccw(c97,3) 97,0.9 ccw(c97,3)
  pour cut-out: 5.1,3 ccw(c3,3) 3,5.1 ccw(c3,3) 0.9,3 ccw(c3,3) 3,0.9 ccw(c3,3)
  pour cut-out: 5.1,47 ccw(c3,47) 3,49.1 ccw(c3,47) 0.9,47 ccw(c3,47) 3,44.9 ccw(c3,47)
  pour cut-out: 5.1,53 ccw(c3,53) 3,55.1 ccw(c3,53) 0.9,53 ccw(c3,53) 3,50.9 ccw(c3,53)
  pour cut-out: 99.1,47 ccw(c97,47) 97,49.1 ccw(c97,47) 94.9,47 ccw(c97,47) 97,44.9 ccw(c97,47)
  pour cut-out: 99.1,53 ccw(c97,53) 97,55.1 ccw(c97,53) 94.9,53 ccw(c97,53) 97,50.9 ccw(c97,53)
  pour cut-out: 99.1,97 ccw(c97,97) 97,99.1 ccw(c97,97) 94.9,97 ccw(c97,97) 97,94.9 ccw(c97,97)
  pour cut-out: 5.1,97 ccw(c3,97) 3,99.1 ccw(c3,97) 0.9,97 ccw(c3,97) 3,94.9 ccw(c3,97)
  text "Tx_433MHz V2.0" at 37.866,96.425 h2
  text "01/04" at 6.934,96.175 h2
  text "Rx_433MHz V2.0" at 37.656,46.5 h2
  text "LAYER TOP 01/02" at 37.5,-35.224 h2.5
  text "LAYER TOP 01/02" at 37.5,-35.224 h2.5
SIGNAL_2:
  text "02/04" at 6.934,96.175 h2
SIGNAL_3:
  text "03/04" at 6.934,96.175 h2
SIGNAL_4:
  text "04/04" at 16.264,96.175 h2
  text "LAYER BOTTOM 02/02" at 62.25,-35.224 h2.5

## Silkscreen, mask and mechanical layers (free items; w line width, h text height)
Top Overlay:
  drawing of 94 lines, arcs and shapes, not listed
  text "SILK SCREEN TOP" at 37.5,-35.224 h2.5
Bottom Overlay:
  text "SILK SCREEN BOTTOM" at 62.25,-35.224 h2.5
Top Paste:
  text "PASTEMASK TOP" at 57.75,-35.224 h2.5
Bottom Paste:
  text "PASTE MASK BOTTOM" at 36.5,-35.224 h2.5
DIELECTRIC_1:
  text "SOLDERMASK TOP" at 57.75,-35.224 h2.5
DIELECTRIC_9:
  text "SOLDERMASK BOTTOM" at 36.5,-35.224 h2.5
Top Assembly:
  text "U100" at 67.25,82.85 h1
  text "U101" at 27.35,75.05 h1
  text "W100" at 90.5,74.7 h1
  text "U102" at 22.3,57 h0.5
  text "X100" at 15.35,55.5 h1 r90
  text "U204" at 24.55,41.7 h1 r90
  text "X201" at 15.4,41.25 h1 r90
  text "U202" at 33.45,29.45 h1 r90
  text "U200" at 63.6,28.35 h1
  text "W200" at 90.4,24.65 h1
  text "H200" at 6.6,23.1 h1
  text "X200" at 40.75,13.85 h1 r90
  text "U203" at 33.55,13 h1 r90
  text "U201" at 60,12.95 h1
  text "H201" at 6.6,9.25 h1
Default User Layer:
  lines w0.025: 1,1 1,49 ; 1,1 85,1 ; 1,1 1,49 ; 1,1 85,1 ; 1,49 85,49 ; 1,49 85,49 ; 1,51 1,99 ; 1,51 85,51 ; 1,51 1,99 ; 1,51 85,51 ; 1,99 85,99 ; 1,99 85,99 ; 85,1 85,49 ; 85,1 85,49 ; 85,51 85,99 ; 85,51 85,99
ESD_Symbol:
  text "PANEL DRAWING" at 37.5,-35.224 h2.5
VSCORE_DETAIL:
  lines w0.1: 0,50 100,50
  text "V-CUTS" at 37.502,-35.224 h2.5
Panel Dimension:
  circle w0.2: c3,47 r1.1
  circle w0.2: c3,53 r1.1
  circle w0.2: c3,97 r1.1
  circle w0.2: c97,97 r1.1
  circle w0.2: c97,53 r1.1
  circle w0.2: c97,47 r1.1
  circle w0.2: c97,3 r1.1
  circle w0.2: c3,3 r1.1
  lines w0.2: 0,50 100,50 ; 0,0 0,100 100,100 100,0 0,0
Single Board Dimensions:
  circle w0.2: c3,3 r1.1
  circle w0.2: c97,3 r1.1
  circle w0.2: c97,47 r1.1
  circle w0.2: c97,53 r1.1
  circle w0.2: c97,97 r1.1
  circle w0.2: c3,97 r1.1
  circle w0.2: c3,53 r1.1
  circle w0.2: c3,47 r1.1
  lines w0.2: 0,50 100,50 ; 0,0 100,0 100,100 0,100 0,0
TitleBlock_Mirrored:
  drawing of 21 lines, arcs and shapes, not listed
  text "PCA NAME:" at 49,-25.989 h1
  text "PCA ID:" at 66,-25.989 h1
  text ".PCA_NAME" at 43.5,-27.28 h2.5
  text ".PCA_ID" at 62.25,-27.722 h2.5
  text "DRAWN BY:" at 66,-29.75 h1
  text ".PCB_AUTHOR" at 60.5,-31.474 h2.5
  text "www.sintecs.nl" at 76.9,-33.485 h1.5
  text "Amarilstraat 14" at 98.6,-33.485 h1.5
  text "LAYER:" at 66,-33.5 h1
  text "info@sintecs.nl" at 77.1,-35.017 h1.5
  text "7554 TV Hengelo (Ov)" at 98.6,-35.017 h1.5
  text "ASSEMBLY DRAWING BOTTOM" at 62.25,-35.224 h2.5
  text "Tel: +31 (0)74 2555 713" at 82.4,-36.717 h1.5
  text "DOC VER:" at 40,-37.239 h1
  text "PCB REV:" at 49,-37.239 h1
  text "PCB ID:" at 66,-37.239 h1
  text "DATE:" at 30.5,-37.25 h1
  text ".YEAR" at 91.401,-37.289 h1
  text "© SINTECS B.V." at 98.6,-37.289 h1
  text "No part of this design or any of its contents may be reproduced," at 98.6,-38.312 h1
  text ".Print_Date" at 27.25,-38.974 h2.5
  text ".PCB_DOC_VER" at 35,-38.974 h2.5
  text ".PCB_ID" at 62.25,-38.972 h2.5
  text ".PCB_REV" at 44,-39 h2.5
  text "copied, modified or adapted, without the prior written consent of Sintecs B.V." at 98.6,-39.322 h1
TittleBlock:
  drawing of 21 lines, arcs and shapes, not listed
  text "PCA ID:" at 34,-25.989 h1
  text "PCA NAME:" at 51,-25.989 h1
  text ".PCA_NAME" at 56.5,-27.28 h2.5
  text ".PCA_ID" at 37.75,-27.722 h2.5
  text "DRAWN BY:" at 34,-29.75 h1
  text ".PCB_AUTHOR" at 39.5,-31.474 h2.5
  text "Amarilstraat 14" at 1.4,-33.485 h1.5
  text "www.sintecs.nl" at 23.1,-33.485 h1.5
  text "LAYER:" at 34,-33.5 h1
  text "7554 TV Hengelo (Ov)" at 1.4,-35.017 h1.5
  text "info@sintecs.nl" at 22.9,-35.017 h1.5
  text "ASSEMBLY DRAWING TOP" at 37.5,-35.224 h2.5
  text "BOARD SHAPE" at 37.5,-35.224 h2.5
  text "Tel: +31 (0)74 2555 713" at 17.6,-36.717 h1.5
  text "PCB ID:" at 34,-37.239 h1
  text "PCB REV:" at 51,-37.239 h1
  text "DOC VER:" at 60,-37.239 h1
  text "DATE:" at 69.5,-37.25 h1
  text "© SINTECS B.V." at 1.4,-37.289 h1
  text ".YEAR" at 8.599,-37.289 h1
  text "No part of this design or any of its contents may be reproduced," at 1.4,-38.312 h1
  text ".PCB_ID" at 37.75,-38.972 h2.5
  text ".PCB_DOC_VER" at 65,-38.974 h2.5
  text ".Print_Date" at 72.75,-38.974 h2.5
  text ".PCB_REV" at 56,-39 h2.5
  text "copied, modified or adapted, without the prior written consent of Sintecs B.V." at 1.4,-39.322 h1
Fab Notes:
  text "MANUFACTURING INFORMATION" at 37.5,-35.224 h2.5
Board:
  text "PANEL DIMENSIONS" at 37.5,-35.224 h2.5
Dimensions:
  text "BOARD DIMENSIONS" at 37.5,-35.224 h2.5
Bottom 3D Body:
  text "3D BODIES BOTTOM" at 62.25,-35.224 h2.5
Top 3D Body:
  text "3D BODIES TOP" at 37.5,-35.224 h2.5

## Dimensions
0,100 to 1.9,97 on Single Board Dimensions
1.9,53 to 0,50 on Single Board Dimensions
0,0 to 3,1.9 on Single Board Dimensions
0,0 to 100,0 on Single Board Dimensions
97,1.9 to 100,0 on Single Board Dimensions
0,0 to 1.9,3 on Single Board Dimensions
0,0 to 0,50 on Single Board Dimensions
0,0 to 0,100 on Single Board Dimensions
0,50 to 1.9,47 on Single Board Dimensions
3,3 to 5.6,4.3 on Single Board Dimensions
0,0 to 0,100 on Panel Dimension
0,0 to 100,0 on Panel Dimension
